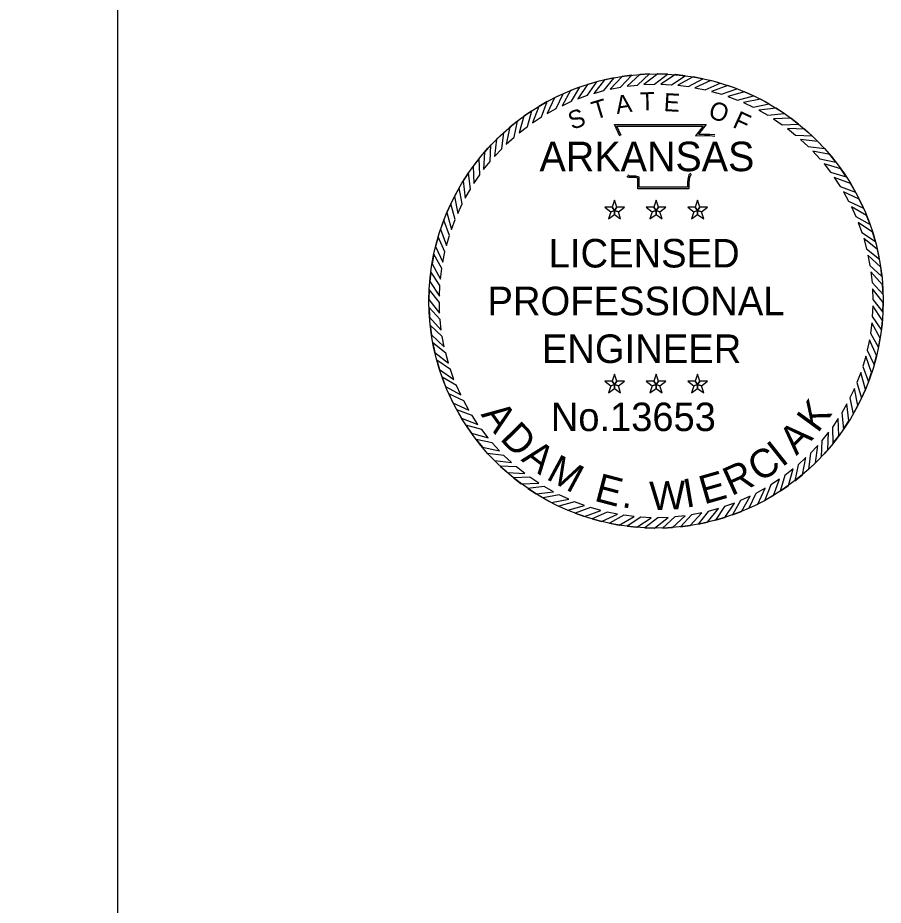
# Model space of a CAD drawing. Extents: x 0 to 19, y -0.6 to 11.3.
# Drawn here: x 16.736 to 19.022, y 5.313 to 7.658 of the extents above; entities that cross this region are included whole.
import ezdxf

# ---------------------------------------------------------------- set-up
doc = ezdxf.new("R2010")
doc.units = 0
for name, color, linetype in [('G-ANNO-STMP', 7, 'Continuous'), ('G-Border-Paper', 7, 'Continuous'), ('G-No Plot-Stamp-2', 7, 'Continuous')]:
    doc.layers.add(name, color=color, linetype=linetype)

msp = doc.modelspace()

# ---------------------------------------------------------------- linework, layer by layer
at = {"layer": 'G-ANNO-STMP'}
for points in [[(18.3581, 7.5062), (18.3325, 7.5029), (18.3011, 7.4693), (18.3285, 7.4745)], [(18.4051, 7.5094), (18.3793, 7.5081), (18.3454, 7.477), (18.3731, 7.4801)], [(18.4522, 7.5089), (18.4264, 7.5096), (18.3902, 7.4813), (18.418, 7.4822)], [(18.4991, 7.5047), (18.4735, 7.5074), (18.4351, 7.4821), (18.463, 7.4808)], [(18.2656, 7.4888), (18.2408, 7.4815), (18.2151, 7.4434), (18.2413, 7.4529)], [(18.3115, 7.4993), (18.2862, 7.494), (18.2576, 7.458), (18.2845, 7.4654)], [(18.5456, 7.4968), (18.5202, 7.5016), (18.48, 7.4793), (18.5077, 7.4758)], [(18.5913, 7.4853), (18.5664, 7.4921), (18.5245, 7.473), (18.5518, 7.4674)], [(18.1769, 7.4572), (18.1536, 7.4461), (18.1341, 7.4044), (18.1585, 7.4179)], [(18.2206, 7.4747), (18.1965, 7.4655), (18.1738, 7.4255), (18.1992, 7.437)], [(18.6359, 7.4703), (18.6116, 7.479), (18.5684, 7.4632), (18.5952, 7.4555)], [(18.6793, 7.4518), (18.6557, 7.4624), (18.6114, 7.4501), (18.6375, 7.4402)], [(18.1347, 7.4362), (18.1123, 7.4234), (18.0962, 7.3803), (18.1195, 7.3956)], [(18.721, 7.43), (18.6984, 7.4423), (18.6532, 7.4336), (18.6784, 7.4217)], [(18.0942, 7.412), (18.0729, 7.3975), (18.0603, 7.3533), (18.0823, 7.3704)], [(18.7609, 7.4049), (18.7393, 7.419), (18.6936, 7.4138), (18.7178, 7.4)], [(18.7987, 7.3768), (18.7783, 7.3926), (18.7323, 7.391), (18.7554, 7.3753)], [(18.0558, 7.3848), (18.0357, 7.3686), (18.0266, 7.3235), (18.0472, 7.3423)], [(18.8342, 7.3458), (18.8151, 7.3632), (18.7692, 7.3652), (18.7909, 7.3477)], [(18.0197, 7.3545), (18.0009, 7.3368), (17.9953, 7.2912), (18.0144, 7.3115)], [(17.986, 7.3216), (17.9687, 7.3025), (17.9667, 7.2565), (17.9841, 7.2783)], [(18.8672, 7.3122), (18.8495, 7.3309), (18.8038, 7.3365), (18.8242, 7.3175)], [(18.8974, 7.276), (18.8812, 7.2961), (18.8361, 7.3053), (18.8549, 7.2847)], [(17.955, 7.2861), (17.9393, 7.2657), (17.9409, 7.2197), (17.9565, 7.2428)], [(18.9247, 7.2376), (18.9101, 7.2589), (18.8659, 7.2716), (18.883, 7.2496)], [(17.9269, 7.2483), (17.9128, 7.2267), (17.918, 7.181), (17.9318, 7.2052)], [(18.9489, 7.1972), (18.936, 7.2196), (18.893, 7.2357), (18.9083, 7.2124)], [(17.9019, 7.2084), (17.8895, 7.1857), (17.8983, 7.1406), (17.9102, 7.1658)], [(18.3125, 7.1485), (18.3187, 7.157), (18.3125, 7.176), (18.3064, 7.157)], [(18.4222, 7.1485), (18.4284, 7.157), (18.4222, 7.176), (18.4161, 7.157)], [(18.532, 7.1485), (18.5381, 7.157), (18.532, 7.176), (18.5258, 7.157)], [(18.9698, 7.155), (18.9588, 7.1783), (18.9171, 7.1977), (18.9305, 7.1733)], [(17.88, 7.1666), (17.8695, 7.1431), (17.8818, 7.0988), (17.8916, 7.1248)], [(18.3125, 7.1485), (18.3064, 7.157), (18.2864, 7.157), (18.3026, 7.1453)], [(18.3125, 7.1485), (18.3225, 7.1453), (18.3386, 7.157), (18.3187, 7.157)], [(18.4222, 7.1485), (18.4161, 7.157), (18.3962, 7.157), (18.4123, 7.1453)], [(18.4222, 7.1485), (18.4322, 7.1453), (18.4483, 7.157), (18.4284, 7.157)], [(18.532, 7.1485), (18.5258, 7.157), (18.5059, 7.157), (18.522, 7.1453)], [(18.532, 7.1485), (18.5419, 7.1453), (18.5581, 7.157), (18.5381, 7.157)], [(18.9874, 7.1113), (18.9782, 7.1354), (18.9382, 7.158), (18.9496, 7.1326)], [(18.3125, 7.1485), (18.3026, 7.1453), (18.2964, 7.1263), (18.3125, 7.1381)], [(18.3125, 7.1485), (18.3125, 7.1381), (18.3286, 7.1263), (18.3225, 7.1453)], [(18.4222, 7.1485), (18.4123, 7.1453), (18.4061, 7.1263), (18.4222, 7.1381)], [(18.4222, 7.1485), (18.4222, 7.1381), (18.4384, 7.1263), (18.4322, 7.1453)], [(18.532, 7.1485), (18.522, 7.1453), (18.5158, 7.1263), (18.532, 7.1381)], [(18.532, 7.1485), (18.532, 7.1381), (18.5481, 7.1263), (18.5419, 7.1453)], [(17.8615, 7.1233), (17.8529, 7.099), (17.8686, 7.0558), (17.8764, 7.0825)], [(19.0015, 7.0663), (18.9942, 7.0911), (18.9561, 7.1168), (18.9655, 7.0905)], [(17.8465, 7.0786), (17.8398, 7.0537), (17.8588, 7.0119), (17.8645, 7.0392)], [(19.012, 7.0204), (19.0067, 7.0456), (18.9707, 7.0742), (18.978, 7.0474)], [(17.835, 7.0329), (17.8303, 7.0076), (17.8526, 6.9674), (17.856, 6.995)], [(19.0188, 6.9738), (19.0155, 6.9993), (18.9819, 7.0307), (18.9871, 7.0033)], [(17.8272, 6.9865), (17.8244, 6.9608), (17.8498, 6.9225), (17.8511, 6.9503)], [(19.022, 6.9267), (19.0207, 6.9525), (18.9897, 6.9864), (18.9927, 6.9587)], [(19.0215, 6.8796), (19.0223, 6.9054), (18.994, 6.9417), (18.9948, 6.9138)], [(17.823, 6.9396), (17.8222, 6.9138), (17.8505, 6.8775), (17.8497, 6.9054)], [(19.0173, 6.8327), (19.0201, 6.8584), (18.9947, 6.8967), (18.9934, 6.8689)], [(17.8225, 6.8925), (17.8237, 6.8667), (17.8548, 6.8328), (17.8518, 6.8605)], [(19.0095, 6.7863), (19.0142, 6.8116), (18.9919, 6.8518), (18.9884, 6.8242)], [(17.8256, 6.8454), (17.829, 6.8199), (17.8626, 6.7885), (17.8574, 6.8159)], [(18.998, 6.7406), (19.0047, 6.7655), (18.9856, 6.8073), (18.98, 6.78)], [(17.8325, 6.7988), (17.8378, 6.7736), (17.8738, 6.745), (17.8665, 6.7718)], [(17.843, 6.7529), (17.8503, 6.7281), (17.8884, 6.7024), (17.879, 6.7287)], [(18.9829, 6.6959), (18.9916, 6.7202), (18.9759, 6.7634), (18.9681, 6.7367)], [(17.8571, 6.7079), (17.8663, 6.6838), (17.9063, 6.6612), (17.8949, 6.6866)], [(18.3125, 6.6891), (18.3187, 6.6976), (18.3125, 6.7165), (18.3064, 6.6976)], [(18.4222, 6.6891), (18.4284, 6.6976), (18.4222, 6.7165), (18.4161, 6.6976)], [(18.532, 6.6891), (18.5381, 6.6976), (18.532, 6.7165), (18.5258, 6.6976)], [(18.9645, 6.6526), (18.975, 6.6761), (18.9627, 6.7204), (18.9529, 6.6944)], [(18.3125, 6.6891), (18.3064, 6.6976), (18.2864, 6.6976), (18.3026, 6.6858)], [(18.3125, 6.6891), (18.3026, 6.6858), (18.2964, 6.6669), (18.3125, 6.6786)], [(18.3125, 6.6891), (18.3225, 6.6858), (18.3386, 6.6976), (18.3187, 6.6976)], [(18.3125, 6.6891), (18.3125, 6.6786), (18.3286, 6.6669), (18.3225, 6.6858)], [(18.4222, 6.6891), (18.4161, 6.6976), (18.3962, 6.6976), (18.4123, 6.6858)], [(18.4222, 6.6891), (18.4123, 6.6858), (18.4061, 6.6669), (18.4222, 6.6786)], [(18.4222, 6.6891), (18.4322, 6.6858), (18.4483, 6.6976), (18.4284, 6.6976)], [(18.4222, 6.6891), (18.4222, 6.6786), (18.4384, 6.6669), (18.4322, 6.6858)], [(18.532, 6.6891), (18.5258, 6.6976), (18.5059, 6.6976), (18.522, 6.6858)], [(18.532, 6.6891), (18.522, 6.6858), (18.5158, 6.6669), (18.532, 6.6786)], [(18.532, 6.6891), (18.5419, 6.6858), (18.5581, 6.6976), (18.5381, 6.6976)], [(18.532, 6.6891), (18.532, 6.6786), (18.5481, 6.6669), (18.5419, 6.6858)], [(17.8747, 6.6642), (17.8857, 6.6409), (17.9274, 6.6215), (17.914, 6.6459)], [(18.9426, 6.6108), (18.955, 6.6335), (18.9462, 6.6786), (18.9343, 6.6534)], [(18.9176, 6.5709), (18.9317, 6.5925), (18.9265, 6.6382), (18.9127, 6.614)], [(17.8956, 6.622), (17.9085, 6.5996), (17.9515, 6.5835), (17.9362, 6.6068)], [(18.8895, 6.5331), (18.9052, 6.5535), (18.9036, 6.5995), (18.888, 6.5764)], [(17.9198, 6.5816), (17.9344, 6.5603), (17.9786, 6.5476), (17.9615, 6.5696)], [(17.9471, 6.5432), (17.9633, 6.5231), (18.0083, 6.5139), (17.9896, 6.5345)], [(18.8585, 6.4976), (18.8758, 6.5167), (18.8778, 6.5627), (18.8604, 6.5409)], [(18.8248, 6.4647), (18.8436, 6.4824), (18.8492, 6.528), (18.8301, 6.5077)], [(17.9773, 6.507), (17.995, 6.4883), (18.0407, 6.4827), (18.0203, 6.5017)], [(18.7887, 6.4344), (18.8088, 6.4506), (18.8179, 6.4957), (18.7973, 6.4769)], [(18.0103, 6.4734), (18.0294, 6.456), (18.0753, 6.454), (18.0536, 6.4715)], [(18.7503, 6.4072), (18.7716, 6.4217), (18.7842, 6.4659), (18.7622, 6.4488)], [(18.0458, 6.4424), (18.0662, 6.4266), (18.1122, 6.4282), (18.0891, 6.4439)], [(18.7098, 6.383), (18.7322, 6.3958), (18.7483, 6.4389), (18.725, 6.4236)], [(18.0836, 6.4143), (18.1052, 6.4002), (18.1509, 6.4054), (18.1267, 6.4192)], [(18.6676, 6.362), (18.6909, 6.3731), (18.7104, 6.4148), (18.6859, 6.4013)], [(18.1235, 6.3892), (18.1461, 6.3769), (18.1913, 6.3856), (18.166, 6.3975)], [(18.1652, 6.3674), (18.1888, 6.3568), (18.2331, 6.3691), (18.207, 6.379)], [(18.6239, 6.3445), (18.648, 6.3537), (18.6707, 6.3937), (18.6453, 6.3822)], [(18.2086, 6.3489), (18.2329, 6.3402), (18.2761, 6.356), (18.2493, 6.3637)], [(18.533, 6.3199), (18.5583, 6.3252), (18.5869, 6.3612), (18.56, 6.3538)], [(18.5789, 6.3304), (18.6037, 6.3377), (18.6294, 6.3758), (18.6032, 6.3663)], [(18.2532, 6.3339), (18.2781, 6.3271), (18.32, 6.3462), (18.2927, 6.3518)], [(18.2989, 6.3224), (18.3243, 6.3176), (18.3645, 6.3399), (18.3368, 6.3434)], [(18.3454, 6.3145), (18.371, 6.3118), (18.4094, 6.3371), (18.3815, 6.3384)], [(18.3923, 6.3103), (18.4181, 6.3096), (18.4543, 6.3379), (18.4265, 6.337)], [(18.4394, 6.3098), (18.4652, 6.3111), (18.4991, 6.3422), (18.4714, 6.3391)], [(18.4864, 6.313), (18.512, 6.3163), (18.5434, 6.3499), (18.516, 6.3447)]]:
    msp.add_lwpolyline(points, close=True, dxfattribs=at)
for points in [[(18.3261, 7.3451), (18.3121, 7.3754), (18.5542, 7.3755), (18.5339, 7.3501), (18.5504, 7.3503), (18.5641, 7.3505), (18.5778, 7.349)], [(18.3296, 7.3467), (18.3181, 7.3716), (18.5462, 7.3717), (18.5259, 7.3462), (18.5504, 7.3465), (18.5639, 7.3467), (18.5774, 7.3452)], [(18.5136, 7.2466), (18.5085, 7.2425), (18.5067, 7.236), (18.5053, 7.223), (18.5053, 7.2099), (18.3779, 7.2099), (18.3779, 7.2286), (18.3779, 7.2365), (18.3691, 7.2391), (18.3514, 7.2391), (18.3491, 7.2426)], [(18.516, 7.2437), (18.5119, 7.2403), (18.5105, 7.2353), (18.5091, 7.2227), (18.5091, 7.206), (18.374, 7.206), (18.374, 7.2286), (18.374, 7.2336), (18.3686, 7.2353), (18.3493, 7.2353), (18.3459, 7.2405)]]:
    msp.add_lwpolyline(points, dxfattribs=at)
at = {"layer": 'G-Border-Paper'}
msp.add_lwpolyline([(17, 11), (0, 11), (0, 0), (17, 0)], close=True, dxfattribs=at)
at = {"layer": 'G-No Plot-Stamp-2'}
msp.add_circle((18.4222, 6.9096), 0.6, dxfattribs=at)

# ---------------------------------------------------------------- texts
at = {"layer": 'G-ANNO-STMP'}
for s, height, rotation, p in [('T', 0.0477, 1.4789, (18.3804, 7.4129)), ('E', 0.0477, 356.672, (18.4415, 7.4114)), ('T', 0.0477, 16.9015, (18.2608, 7.3882)), ('A', 0.0477, 8.6788, (18.3187, 7.4034)), ('O', 0.0477, 341.2218, (18.5574, 7.395)), ('S', 0.0477, 19.7726, (18.2001, 7.361)), ('F', 0.0477, 335.3628, (18.6218, 7.3699)), ('K', 0.0754, 53.8471, (18.8495, 6.5585)), ('A', 0.0754, 305.982, (17.958, 6.6093)), ('D', 0.0754, 314.3022, (18.0075, 6.5441)), ('A', 0.0754, 45.185, (18.7929, 6.4994)), ('A', 0.0754, 322.6223, (18.0634, 6.4889)), ('C', 0.0754, 32.1396, (18.695, 6.4289)), ('I', 0.0754, 38.4057, (18.7549, 6.4687)), ('M', 0.0754, 331.7969, (18.1293, 6.4402)), ('R', 0.0754, 24.1616, (18.6211, 6.3937)), ('E', 0.0754, 345.2782, (18.2564, 6.3823)), ('E', 0.0754, 16.0125, (18.5491, 6.3716)), ('W', 0.0754, 2.1127, (18.4063, 6.3565)), ('I', 0.0754, 9.5753, (18.5011, 6.363)), ('.', 0.0754, 350.8583, (18.3296, 6.3653))]:
    msp.add_text(s, height=height, rotation=rotation, dxfattribs=at).set_placement(p)
for s, height, p in [('ARKANSAS', 0.07792, (18.1143, 7.2524)), ('LICENSED', 0.07543, (18.1385, 6.998)), ('PROFESSIONAL', 0.075433, (17.9768, 6.8719)), ('ENGINEER', 0.07543, (18.1205, 6.7457)), ('No.13653', 0.07514, (18.1443, 6.5659))]:
    msp.add_text(s, height=height, dxfattribs=at).set_placement(p)

doc.saveas('drawing.dxf')
